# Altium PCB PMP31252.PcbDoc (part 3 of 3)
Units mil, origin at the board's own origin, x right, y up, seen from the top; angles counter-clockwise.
Board outline 4527.56 x 3188.98 mil, 6 copper layers (Top Layer, Layer 1, Layer 3, Layer 4, Layer 2, Bottom Layer), stack 32.112 mil thick; 215 components, 83 nets, 499 pads, 1248 vias.
Unrouted connection lines stored in the file: 2.
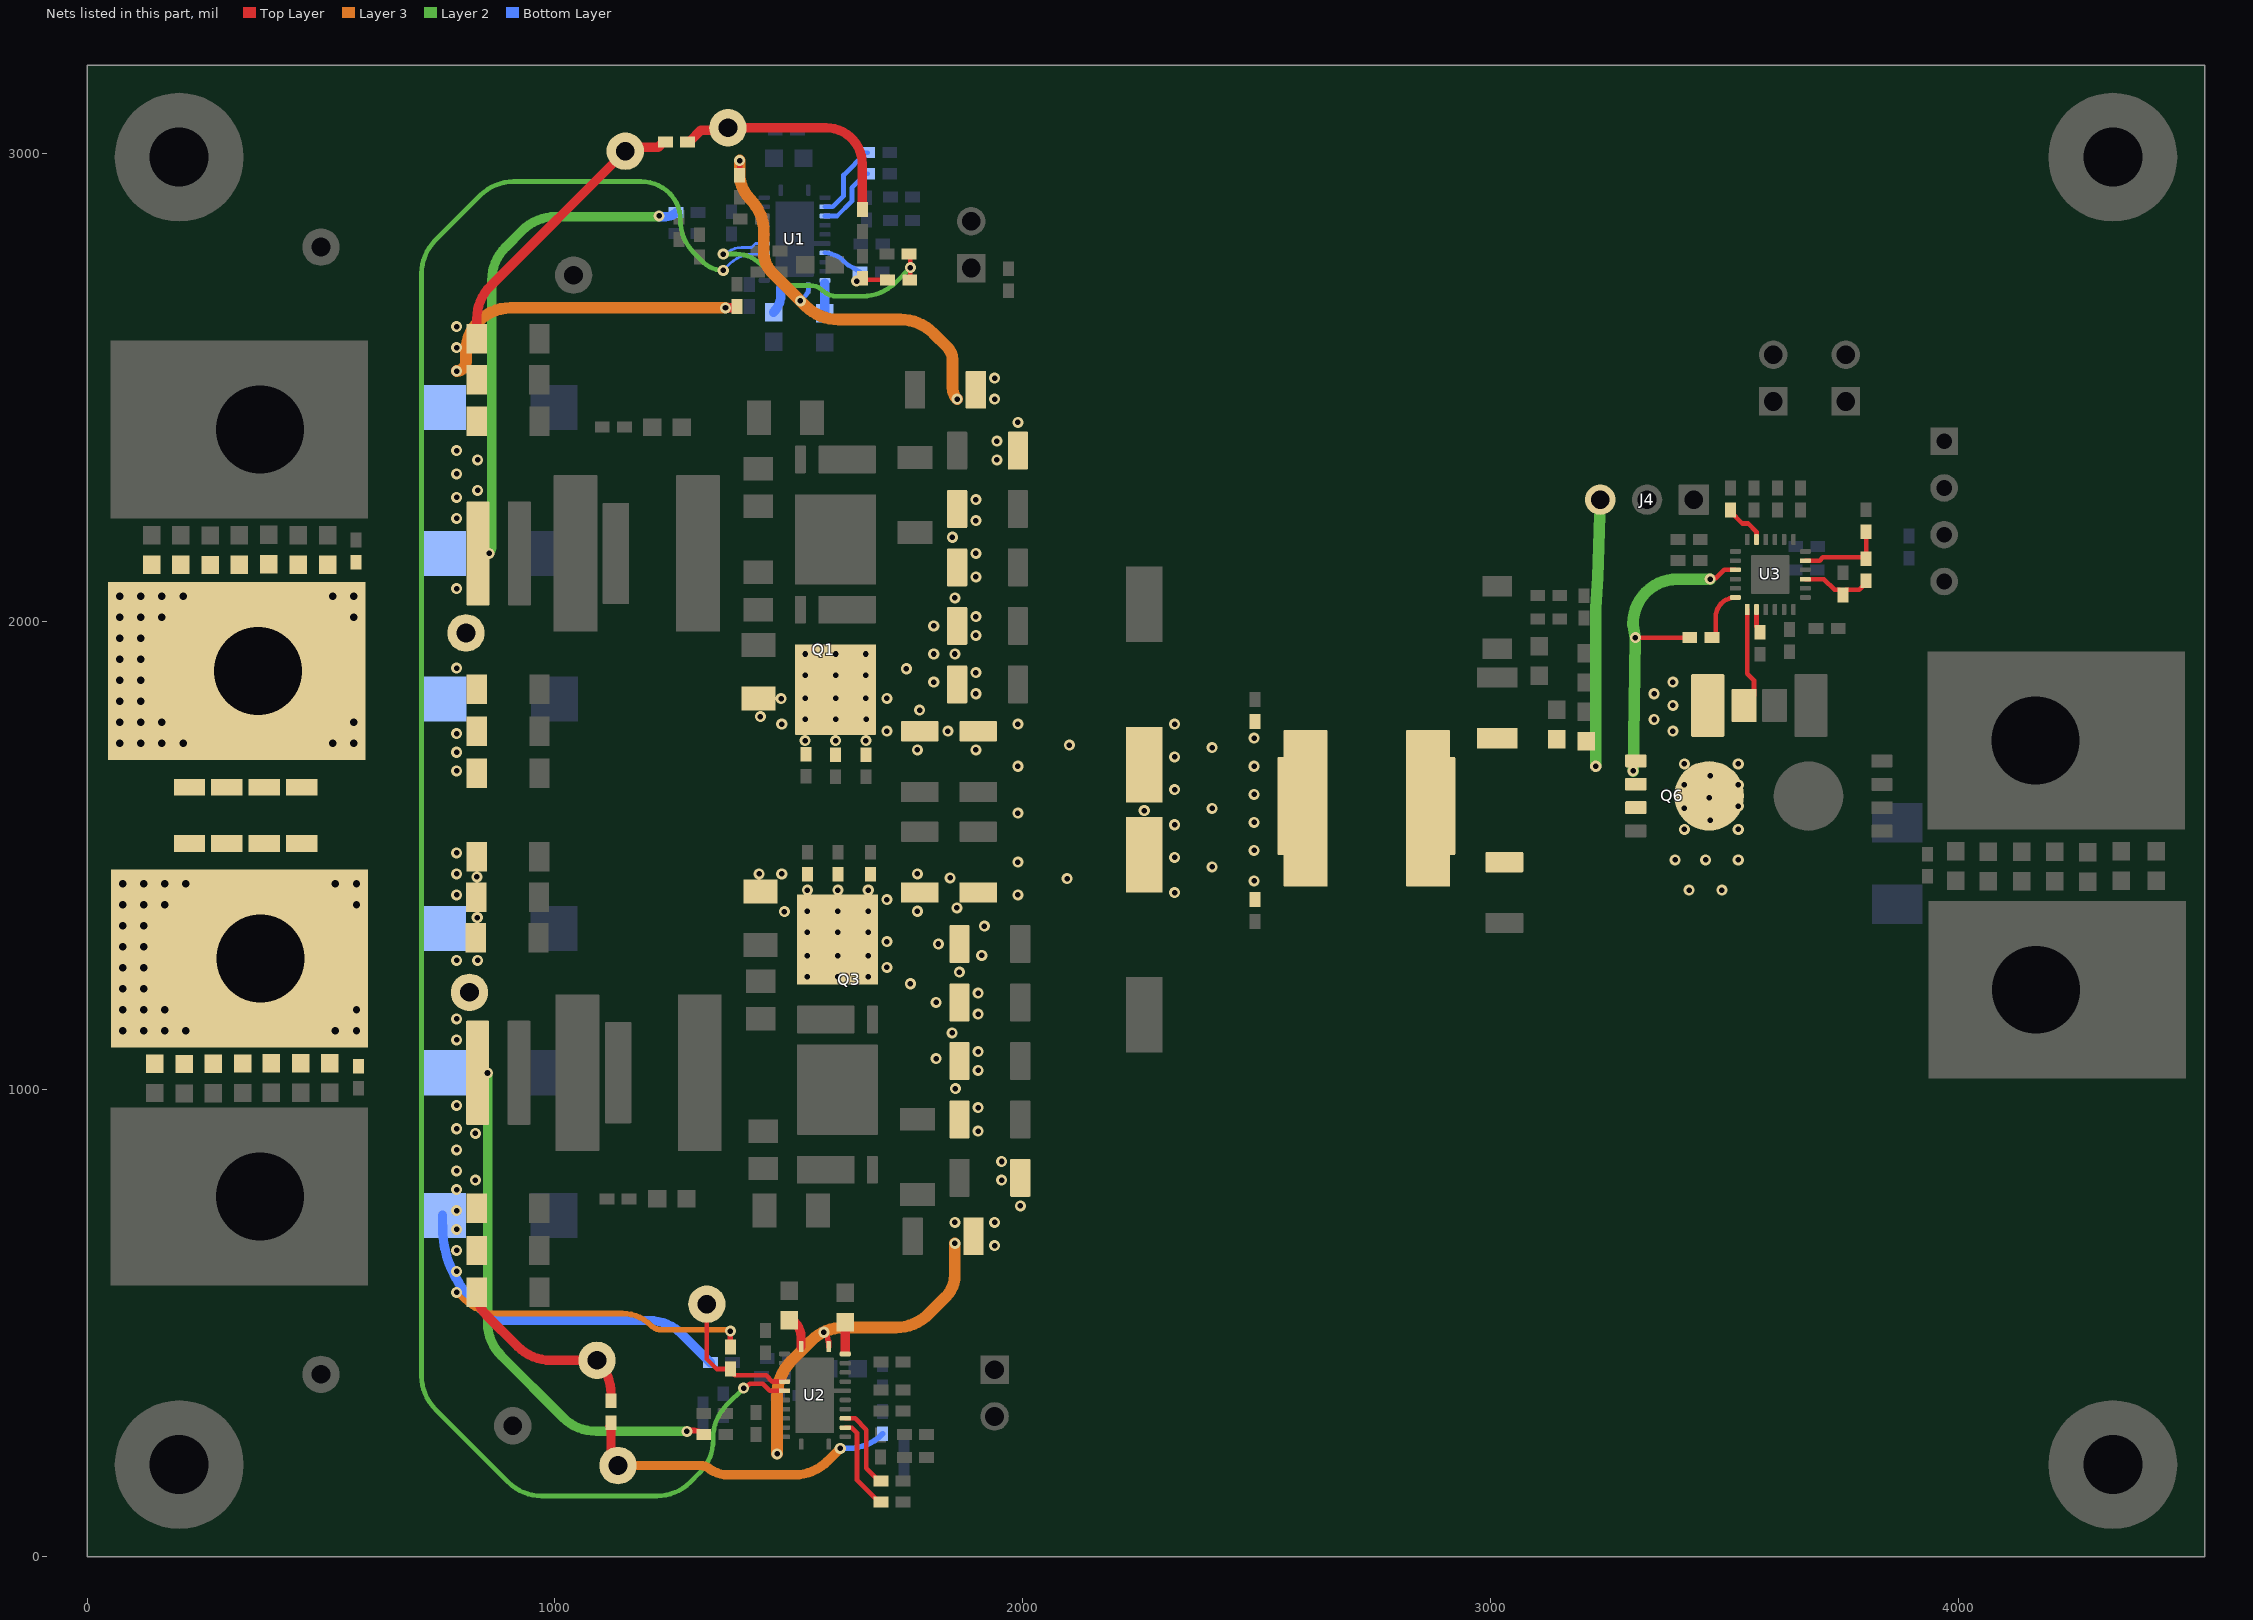
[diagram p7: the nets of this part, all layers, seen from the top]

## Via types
v1: diameter 23.62, hole 11.81, Top Layer to Bottom Layer, tented both sides, 1061 vias
v2: diameter 32, hole 16, Top Layer to Bottom Layer, 168 vias
v3: diameter 19.68, hole 7.87, Top Layer to Bottom Layer, 16 vias
v4: diameter 23.62/23.62/23.62/23.62/23.62/23.62 (per signal layer), hole 11.81, Top Layer to Bottom Layer, tented both sides, 3 vias

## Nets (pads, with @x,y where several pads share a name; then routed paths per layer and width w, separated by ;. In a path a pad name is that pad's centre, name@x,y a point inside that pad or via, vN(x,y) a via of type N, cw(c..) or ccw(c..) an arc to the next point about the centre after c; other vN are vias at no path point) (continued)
NetQ6_5: Q6.5 R56.2 R68.2 U3.19 | length 219.8
  Top Layer w10: R56.2@3542.52,1820 3563.48,1840.96 3563.48,1873.73 3549.29,1887.91 U3.19@3549.29,2025.2
  other v1: 3425,1425 3495,1425 3395,1490 3460,1490 3530,1490 3415,1555 3530,1555 3470,1575 3415,1600 3530,1605 3468.12,1623.09 3415,1650 3530,1650 3470,1670 3415,1695 3530,1695 3390,1765 3350,1790 3390,1820 3350,1845 3390,1870
NetR4_1: R4.1 U1.13 | length 56.5
  Bottom Layer w20: R4.1@1467.56,2660.43 ccw(c1430.21,2697.79) 1483.03,2697.79 U1.13@1483.03,2712.83
NetR9_1: R9.1 U1.11 | length 63.5
  Bottom Layer w20: R9.1@1576.75,2658.93 1576.75,2722.44
NetR12_1: R12.1 R16.2 TP2.1 | length 527
  Top Layer w20: R12.1@1283.62,3025 1287.56,3025 1312.56,3050 1365,3050 TP2.1@1370,3055 1580,3055 cw(c1580,2977.95) 1657.05,2977.95 R16.2@1657.05,2880.79
NetR19_2: R19.2 U1.4 | length 145.5
  Bottom Layer w10: U1.4@1577.52,2866.38 1603.12,2866.38 1635.18,2898.43 1635.18,2926.91 1664.96,2956.69 R19.2@1668.9,2956.69
NetR20_2: R20.2 U1.3 | length 165.4
  Bottom Layer w10: U1.3@1577.52,2886.06 1593.93,2886.06 1617.18,2909.31 1617.18,2953.91 1664.96,3001.69 R20.2@1668.9,3001.69
NetR36_1: R36.1 U2.13 | length 54.7
  Top Layer w20: R36.1@1513.55,500.61 cw(c1482.68,469.73) 1526.34,469.73 U2.13@1526.34,449.33
NetR39_1: R39.1 TP4.1 U2.17 | length 305.4
  Top Layer w10: TP4.1@1325,540 1325,422.76 1346.38,401.38 R39.1@1375,401.38 1375,397.44 1384.44,388 1451.61,388 1465.01,374.61 1490.83,374.61 U2.17@1490.91,374.53
NetR41_1: R41.1 U2.11 | length 60
  Top Layer w20: 1620.87,441.77 R41.1@1620.87,501.77
NetR46_1: R46.1 R50.1 TP6.1 | length 731.3
  Top Layer w10: R46.1@1112.68,279.06 1113.19,279.06 R46.1@1120,286.38 ; TP6.1@1135,195 1147.1,200.01 1148.51,201.42 TP6.1@1148.9,201.81
  Top Layer w20: R46.1@1120,286.38 1120,231.21 ccw(c1171.21,231.21) TP6.1@1135,195
  Layer 3 w20: TP6.1@1135,195 1310.86,195 cw(c1310.86,160.86) 1325.67,191.62 ; 1335,185 ccw(c1310.86,160.86) 1325.67,191.62 ; v1(1610.13,231.7) 1582.71,204.29 cw(c1512,275) 1512,175 1370.32,175 cw(c1370.32,243.28) 1325.67,191.62
  Bottom Layer w12: v1(1610.13,231.7) 1628,231.7 ccw(c1628,331.7) 1698.71,260.99 R50.1@1700.87,263.15
NetR47_2: R47.2 U2.3 | length 201.7
  Top Layer w10: U2.3@1620.83,276.1 1620.91,276.02 1635.18,276.02 1645.87,265.34 1645.87,164.21 1693.31,116.77 R47.2@1697.24,116.77
NetR48_2: R48.2 U2.4 | length 180.2
  Top Layer w10: U2.4@1620.83,295.79 1641.74,295.79 1665.87,271.66 1665.87,189.21 1693.31,161.77 R48.2@1697.24,161.77
NetR58_1: R58.1 U3.20 | length 56.1
  Top Layer w10: U3.20@3568.98,2025.2 3568.98,1988.58 3580,1977.56 R58.1@3580,1973.62
NetR60_2: R60.2 R61.2 U3.3 | length 159.6
  Top Layer w10: U3.3@3673.31,2090.16 3702.59,2090.16 3702.93,2089.81 3713.13,2089.81 3735.82,2067.13 3746.69,2067.13 R60.2@3753.5,2060.31 ; R60.2@3753.5,2056.38 R60.2@3753.5,2060.31 ; R61.2@3803.5,2086.38 3803.5,2082.44 3788.19,2067.13 3760.31,2067.13 R60.2@3753.5,2060.31
NetR61_1: R61.1 R62.2 U3.5 | length 192.1
  Top Layer w10: U3.5@3673.31,2129.53 3703.83,2129.53 3710.89,2136.58 3800.54,2136.58 R61.1@3803.5,2133.62 R62.2@3803.5,2191.38
NetR66_2: R66.2 U3.11 | length 93.4
  Top Layer w10: R66.2@3513.5,2237.76 3513.5,2233.82 3538.31,2209.01 3550.99,2209.01 3568.9,2191.1 3568.9,2174.88 U3.11@3568.98,2174.8
NetR71_1: R71.1 U3.18 | length 108.3
  Top Layer w10: R71.1@3481.65,1966.53 3481.65,2008.74 cw(c3523.7,2008.74) U3.18@3523.7,2050.79
PFM/SNYC: R21.2 R22.2 U1.18 | length 601.3
  Top Layer w10: R21.2@1757.24,2785 cw(c1750.53,2778.28) 1760.03,2778.28 v1(1760,2755.99) ; R22.2@1760,2730.03 v1(1760,2755.99)
  Layer 2 w10: v1(1360,2785) 1387.98,2785 cw(c1387.98,2711.8) 1439.74,2763.56 1479.01,2724.29 ccw(c1494.35,2739.63) 1494.35,2717.94 1546.03,2717.94 cw(c1546.03,2680.36) 1572.6,2706.93 ccw(c1601.4,2735.73) 1601.4,2695 1657.59,2695 ccw(c1657.59,2795) 1728.3,2724.29 v1(1760,2755.99)
  Bottom Layer w6: v1(1360,2785) 1365,2785 cw(c1399.05,2750.95) 1399.05,2799.11 1420.68,2799.11 1428.89,2807.32 U1.18@1447.6,2807.32
SYNC: U1.17 U2.18 | length 4349.1
  Top Layer w10: v1(1403.69,360.64) 1407.37,360.64 1416.73,370 1444.16,370 1459.24,354.92 1490.83,354.92 U2.18@1490.91,354.84
  Layer 2 w10: v1(1360,2750) cw(c1360,2810.35) 1317.33,2767.68 1297.19,2787.81 cw(c1368.29,2858.13) 1268.29,2858.13 1268.29,2858.77 ccw(c1188.77,2858.77) 1245,2915 ccw(c1184.64,2854.64) 1184.64,2940 911.42,2940 ccw(c911.42,2840) 840.71,2910.71 744.29,2814.29 ccw(c815,2743.58) 715,2743.58 715,386.42 ccw(c815,386.42) 744.29,315.71 900.71,159.29 ccw(c971.42,230) 971.42,130 1218.58,130 ccw(c1218.58,230) 1289.29,159.29 1309.11,179.11 ccw(c1238.4,249.82) 1338.4,249.82 1338.4,253.94 cw(c1438.4,253.94) 1348.81,298.37 cw(c1438.4,253.94) 1352.47,305.09 cw(c1438.4,253.94) 1367.69,324.65 v1(1403.69,360.64)
  Bottom Layer w6: v1(1360,2750) 1374.56,2764.56 ; 1374.58,2764.58 cw(c1422.82,2716.31) 1422.82,2784.55 1440.15,2784.55 ccw(c1440.15,2795.09) U1.17@1447.6,2787.64
VDDA: C25.1 R13.2 R22.1 U1.8 | length 165.9
  Top Layer w10: R13.2@1657.52,2733.07 ccw(c1664.93,2740.48) 1664.93,2730 R22.1@1711.38,2730
  Bottom Layer w10: U1.8@1577.52,2787.64 1589.73,2785.69 cw(c1587.36,2770.91) 1592.88,2784.82 1601.54,2781.39 cw(c1586.73,2744.02) 1614.67,2772.92 1624.58,2763.34 1625.31,2762.74 ccw(c1636.68,2776.69) 1628.12,2760.86 1641.77,2753.5 C25.1@1652.52,2746.69 1652.52,2745.35 cw(c1625.1,2745.35) 1644.49,2725.97 ccw(c1643.26,2727.19) v1(1645,2727.19)
Vin_FLT: C1.1 C2.2 C3.2 C4.2 C5.2 C6.2 C7.2 C8.2 C9.1 C28.2 C29.2 C30.2 C31.2 C32.2 C33.2 C34.2 C54.2 C56.2 C59.1 C60.1 C61.1 C62.1 C63.1 C64.1 C73.1 C99.1 L1.2 L6.2 Q1.5-6-7-8 Q3.5-6-7-8 R5.2 R30.2 R32.2 R33.2 U1.12 U2.12 | length 1646.7
  Top Layer w12: R5.2@1395,2953.62 v1(1395,2985) ; v1(1575,480) cw(c1549.91,454.91) 1585.39,454.91 U2.12@1585.39,449.33
  Layer 3 w25: v1(1395,2985) 1395,2956.76 ccw(c1471.67,2956.76) 1417.46,2902.54 cw(c1346.74,2831.83) 1446.74,2831.83 1446.74,2786.87 ccw(c1503.76,2786.87) 1463.44,2746.56 v1(1525,2685) 1535.71,2674.29 ccw(c1606.42,2745) 1606.42,2645 1738.58,2645 cw(c1738.58,2545) 1809.29,2615.71 1839.39,2585.61 cw(c1813.79,2560) 1850,2560 1850,2499.14 ccw(c1884.14,2499.14) v1(1860,2475) ; v1(1475,220) 1475,343.26 1475,343.33 cw(c1584.04,343.33) 1506.94,420.44 1548.31,461.81 cw(c1616.42,393.62) 1616.42,490 1728.58,490 ccw(c1728.58,590) 1799.29,519.29 1835.86,555.86 ccw(c1789.64,602.07) 1855,602.07 v1(1855,670)
  Bottom Layer w10: v1(1525,2685) 1534.49,2694.49 ccw(c1516.14,2712.83) U1.12@1542.09,2712.83
  Bottom Layer w12: v1(1475,220) R33.2@1475,256.38
  other v1: 1940,665 1855,715 1940,715 1995,750 1955,805 1955,845 1905,910 1905,960 1856.1,1000.71 1905,1040 1815,1065 1905,1080 1849.15,1119.86 1905,1160 1815,1185 1905,1205 1760,1225 1540,1240 1605,1240 1670,1240 1865,1250 1710,1260 1540,1285 1605,1285 1670,1285 1912.63,1285.85 1820,1310 1710,1315 1540,1335 1605,1335 1670,1335 1918.03,1348.2 1490.63,1379.05 1539.62,1379.58 1604.62,1379.58 1669.62,1379.58 1775,1380 1859.57,1387.05 1710,1405 1990,1415 2325,1420 1540,1425 1605,1425 1670,1425 2495,1445 2095,1450 1844.9,1451.28 1436.51,1460.02 1485,1460 1775,1460 2405,1475 1990,1485 2325,1495 2495,1510 2325,1565 2495,1570 1990,1590 2260,1595 2405,1600 2495,1630 2325,1640 1990,1690 2495,1690 2325,1710 1775,1725 1900,1725 2405,1730 2100,1735 1535,1745 1600,1745 1665,1745 2495,1750 1710,1765 1840,1765 1485,1780 1990,1780 2325,1780 1535.38,1790.42 1600.38,1790.42 1665.38,1790.42 1439.22,1796.13 1780,1810 1483.59,1834.76 1535,1835 1600,1835 1665,1835 1710,1835 1900,1845 1810,1870 1535,1885 1600,1885 1665,1885 1900,1890 1751.55,1898.43 1535,1930 1600,1930 1665,1930 1810,1930 1855,1930 1900,1970 1810,1990 1900,2010 1855,2050 1900,2095 1900,2145 1849.66,2179.62 1900,2215 1900,2260 1945,2345 1945,2385 1990,2425 1940,2475 1940,2520
VIN_PROT: C10.1 C11.1 C55.1 C101.1 J4.3 L1.1 L6.1 Q6.1 Q6.2 Q6.3 R71.2 U3.15 | length 1283.2
  Top Layer w10: v1(3310,1965) R71.2@3426.38,1965 ; v1(3470,2090) 3472.61,2092.61 3482.61,2092.61 3499.84,2109.84 U3.15@3523.7,2109.84
  Layer 2 w25: v1(3225.29,1690) 3225,1936.86 3225,2028.14 3229.31,2093.72 J4.3@3235,2260 ; v1(3305.29,1680) v1(3310,1965) 3305.39,1990.76 cw(c3330,1995.17) 3305,1994.82 3305,1995 cw(c3400,1995) 3400,2090 v1(3470,2090)
Vout_1: C18.1 C19.1 C20.1 C21.1 C27.1 C57.1 C65.1 C67.1 C68.1 C69.1 C78.1 C79.1 C80.1 C81.1 C82.1 C83.1 C84.1 R6.2 R10.2 R12.2 R25.2 R26.2 R27.2 R28.2 R29.2 T1.1 TP1.1 TP8.1 | length 2391.9
  Top Layer w12: R6.2@835.71,2145 v4(859.3,2145)
  Top Layer w20: C68.1@833.05,2603.97 833.05,2646.05 cw(c933.05,2646.05) 862.34,2716.76 TP1.1@1150.58,3005 1158.71,3013.14 1220.58,3013.14 1232.44,3025 R12.2@1236.38,3025 ; v1(1364.78,2670) 1387.72,2670 1389.53,2671.81 R10.2@1389.53,2673.06
  Layer 2 w12: v4(859.3,2145) ccw(c859.3,2147.77) v4@861.26,2145.81
  Layer 2 w20: v4(859.3,2145) ccw(c845.54,2158.76) 865,2158.76 865,2728.58 cw(c965,2728.58) 894.29,2799.29 930.71,2835.71 cw(c1001.42,2765) 1001.42,2865 1222.4,2865 1222.73,2865.33 v1(1222.73,2866.62)
  Layer 3 w25: v1(790,2535) ccw(c790,2555) 810,2555 810,2575 cw(c905,2575) 905,2670 v1(1364.78,2670)
  Bottom Layer w20: v1(1222.73,2866.62) 1222.75,2865 1237.36,2865 ccw(c1237.36,2895.51) R25.2@1258.94,2873.94
  other v1: 790,1680 790,1720 790,1760 790,1900 790,2070 790,2220 790,2265 835,2280 790,2315 835,2345 790,2365 790,2585 790,2630
  other v2: 70,1738.82 115,1738.82 160,1738.82 205,1738.82 525,1738.82 570,1738.82 70,1783.82 115,1783.82 160,1783.82 570,1783.82 70,1828.82 115,1828.82 70,1873.82 115,1873.82 70,1918.82 115,1918.82 70,1963.82 115,1963.82 70,2008.82 115,2008.82 160,2008.82 570,2008.82 70,2053.82 115,2053.82 160,2053.82 205,2053.82 525,2053.82 570,2053.82
Vout_2: C38.1 C39.1 C40.1 C41.1 C42.1 C58.1 C66.1 C70.1 C71.1 C72.1 C85.1 C86.1 C87.1 C88.1 C89.1 C90.1 C91.1 R26.1 R27.1 R28.1 R29.1 R37.2 R39.2 R40.2 R46.2 R52.2 T3.1 TP5.1 TP10.1 | length 2932
  Top Layer w12: v4@859.78,1034.78 v4@860,1035 ; v1(1282.45,268.26) 1284.18,270 1298.14,270 cw(c1298.14,241.91) R52.2@1318.01,261.77 ; R39.2@1375,448.62 v1(1375,482.3)
  Top Layer w20: C71.1@833.07,565 ccw(c900.84,565) 852.92,517.08 920.71,449.29 ccw(c991.42,520) 991.42,420 TP5.1@1090,420 1090.71,419.29 cw(c1020,348.58) 1120,348.58 R46.2@1120,333.62 ; R37.2@855.62,1033.9 v4(855.95,1034.23)
  Layer 2 w20: v4(855.95,1034.23) ccw(c852.55,1037.63) 856.21,1034.52 856.21,500.21 ccw(c956.21,500.21) 885.5,429.5 1017.45,297.55 ccw(c1088.16,368.26) 1088.16,268.26 v1(1282.45,268.26)
  Layer 3 w12: v1(790,565) 805.71,549.29 ccw(c876.42,620) 876.42,520 1144.64,520 cw(c1144.64,434.64) 1205,495 ccw(c1228.3,518.3) 1228.3,485.35 1373.74,485.35 cw(c1370.69,482.3) v1(1375,482.3)
  Bottom Layer w20: C66.1@759.89,729.85 760.35,691.62 760.35,691.51 ccw(c986.69,705.98) 826.32,545.61 826.39,545.53 844.33,527.6 ccw(c898.88,582.16) 898.88,505 1201.33,505 cw(c1201.33,405) 1272.05,475.71 R40.2@1332.76,415
  other v1: 790,610 790,655 790,700 790,740 790,785 830,805 790,825 790,870 830,905 790,915 790,965 790,1105 790,1150 790,1275 835,1275 834.01,1366.53 790,1415 833.4,1453.48 790,1460 790,1505
  other v2: 75.92,1124.2 120.92,1124.2 165.92,1124.2 210.92,1124.2 530.92,1124.2 575.92,1124.2 75.92,1169.2 120.92,1169.2 165.92,1169.2 575.92,1169.2 75.92,1214.2 120.92,1214.2 75.92,1259.2 120.92,1259.2 75.92,1304.2 120.92,1304.2 75.92,1349.2 120.92,1349.2 75.92,1394.2 120.92,1394.2 165.92,1394.2 575.92,1394.2 75.92,1439.2 120.92,1439.2 165.92,1439.2 210.92,1439.2 530.92,1439.2 575.92,1439.2
pads on no net: U2.1 U2.2 U2.22 U2.23 U2.24 U3.8 U3.17 U3.21 U3.25

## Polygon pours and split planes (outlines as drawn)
GND on Top Layer "NONET_L01_P-001" (solid, pour order 84): 3010.88,3148.33 2925,3148.33 ccw(c2925,3048.33) 2825,3048.33 2825,1860 ccw(c2840,1860) 2840,1845 2945,1845 cw(c2945,1835) 2955,1835 2955,1370 cw(c2940,1370) 2940,1355 2835,1355 ccw(c2835,1330) 2810,1330 2810,110 ccw(c2870,110) 2870,50 4390,50 ccw(c4390,150) 4490,150 4490,3045 ccw(c4390,3045) 4390,3145 4220,3145
NetC37_1 on Top Layer "NONET_L01_P-001" (solid, pour order 57): 1126.88,763.59 1126.88,825.67 cw(c1194.74,825.67) 1146.75,873.66 ccw(c1143.52,870.43) 1143.52,875 1035,875 cw(c1035,814.25) 1095.75,814.25 1095.75,767
NetC37_1 on Top Layer "NONET_L01_P-001" (solid, pour order 7): 898.98,914.78 ccw(c948.98,914.78) 948.98,864.78 1119.78,864.78 ccw(c1119.78,910) 1165,910 1165,1160 ccw(c1119.73,1159.95) 1119.78,1205.22 943.98,1204.78 ccw(c946.48,1157.28) 898.98,1154.78
NetC15_1 on Top Layer "NONET_L01_P-001" (solid, pour order 14): 900,2025 ccw(c950,2025) 950,1975 1120.79,1975 ccw(c1120.79,2020.22) 1166.02,2020.22 1166.02,2270.22 ccw(c1120.75,2270.17) 1120.79,2315.44 945,2315 ccw(c947.5,2267.5) 900,2265
GND on Top Layer "NONET_L01_P-001" (solid, pour order 87): 1510,750 1510,710 cw(c1475,710) 1475,675 1438.28,675 cw(c1431.21,726.21) 1400,685 ccw(c1350.86,634.65) 1350,705 1285,705 1285,50 1815,50 1815,673.58 ccw(c1715,673.58) 1785.71,744.29 1780,750
AGND2 on Top Layer "NONET_L01_P-001" (solid, pour order 30): 1679.37,428.23 1679.37,108.23 ccw(c1694.37,108.23) 1694.37,93.23 1754.37,93.23 ccw(c1754.37,158.23) 1819.37,158.23 1819.37,389.13 ccw(c1770.08,389.14) 1770.08,438.43 1689.57,438.43 ccw(c1689.57,428.23)
GND on Top Layer "NONET_L01_P-001" (solid, pour order 77): 580,1011.22 cw(c578.64,989.86) 600,988.5 600,550 ccw(c665,550) 665,485 859.37,485 ccw(c859.37,525.63) 900,525.63 900,805 cw(c930,805) 930,835 1040,835 cw(c1040,805) 1070,805 1070,735 ccw(c1100,735) 1100,705 1300,705 cw(c1300,605) 1400,605 1400,50 145,50 cw(c145,150) 45,150 45,955 cw(c100,955) 100,1010
GND on Top Layer "NONET_L01_P-001" (solid, pour order 88): 2110,3150 1695,3150 1695,2495 1773.79,2495 ccw(c1773.79,2546.21) 1810,2510 1810,2540 cw(c1845,2540) 1845,2575 1940,2575 cw(c1940,2475) 2040,2475 2040,2445 2110,2445
GND on Top Layer "NONET_L01_P-001" (solid, pour order 86): 2530,1845 ccw(c2530,1830) 2515,1830 2515,1824.26 cw(c2507.53,1824.26) 2507.53,1816.8 1975.01,1816.8 cw(c1975.01,1838.62) 1953.19,1838.62 1953.19,2253.19 cw(c1990,2253.19) 1990,2290 2000,2290 ccw(c2000,2330) 2040,2330 2040,3150 2945,3150 2945,1885 cw(c2905,1885) 2905,1845
GND on Top Layer "NONET_L01_P-001" (solid, pour order 85): 2935,1355 2540,1355 cw(c2540,1370) 2525,1370 ccw(c2520,1370) 2520,1375 2020,1375 ccw(c2020,1305) 1950,1305 1950,920 ccw(c1980,920) 1980,890 2000,890 cw(c2000,855) 2035,855 2035,710 cw(c1935,710) 1935,610 1837.28,610 cw(c1837.28,632.28) 1815,632.28 1815,665 1780,665 cw(c1780,660) 1785,660 1785,50 2935,50
NetC15_1 on Top Layer "NONET_L01_P-001" (solid, pour order 82): 1102.16,2451.89 ccw(c1102.16,2434.73) 1085,2434.73 1085,2345 cw(c1055,2345) 1055,2315 1055,2295 1140,2295 cw(c1140,2309.75) 1125.25,2309.75 1125.25,2315.44 cw(c1125.25,2323.44) 1117.24,2323.44 1117.24,2437.15 ccw(c1102.62,2437.15) 1102.62,2451.77
GND on Top Layer "NONET_L01_P-001" (solid, pour order 80): 1505,2450 1505,2455 ccw(c1465,2455) 1465,2495 1090,2495 ccw(c1090,2465) 1060,2465 1060,2408.69 cw(c1028.59,2408.69) 1028.59,2377.28 922.72,2377.28 cw(c922.72,2400) 900,2400 900,2635 ccw(c835,2635) 835,2700 670,2700 ccw(c670,2630) 600,2630 600,2175 cw(c580,2175) 580,2155 90,2155 cw(c90,2200) 45,2200 45,3049.34 cw(c145,3049.34) 145,3149.34 1750.66,3149.34 cw(c1750.66,3095) 1805,3095 1805,2690 cw(c1745,2690) 1745,2630 1745,2435
GND on Top Layer "NONET_L01_P-001" (solid, pour order 72): 1555,1685 1355,1685 cw(c1355,1725) 1315,1725 1315,1910 ccw(c1275,1910) 1275,1950 905.8,1950 ccw(c905.8,1924.2) 880,1924.2 880,1270 ccw(c910,1270) 910,1240 1320,1240 ccw(c1320,1265) 1345,1265 1345,1460 cw(c1372.5,1462.5) 1370,1490 1555,1490
GND on Top Layer "NONET_L01_P-001" (solid, pour order 39): 1520,860 ccw(c1520,850) 1510,850 1510,650 ccw(c1535,650) 1535,625 1790,625 ccw(c1790,650) 1815,650 1815,830 ccw(c1785,830) 1785,860
Vout_1 on Top Layer "NONET_L01_P-001" (solid, pour order 65): 619.08,2163.02 cw(c594.08,2163.02) 594.08,2138.02 94.08,2138.02 ccw(c94.08,2083.02) 39.08,2083.02 39.08,1653.02 ccw(c79.08,1653.02) 79.08,1613.02 824.08,1613.02 ccw(c824.08,1648.02) 859.08,1648.02 859.08,2638.02 ccw(c829.08,2638.02) 829.08,2668.02 654.08,2668.02 ccw(c654.08,2633.02) 619.08,2633.02
Vout_2 on Top Layer "NONET_L01_P-001" (solid, pour order 64): 625,1010 ccw(c600,1010) 600,1035 100,1035 cw(c100,1090) 45,1090 45,1520 cw(c85,1520) 85,1560 830,1560 cw(c830,1525) 865,1525 865,520 cw(c850,520) 850,505 660,505 cw(c660,540) 625,540
NetC14_1 on Top Layer "NONET_L01_P-001" (solid, pour order 61): 1249.67,2283.33 1249.67,2428.33 cw(c1254.67,2428.33) 1254.67,2433.33 1289.67,2433.33 cw(c1289.67,2428.33) 1294.67,2428.33 1294.67,2333.33 ccw(c1309.67,2333.33) 1309.67,2318.33
NetC35_1 on Top Layer "NONET_L01_P-001" (solid, pour order 58): 1260,890 1260,745 ccw(c1265,745) 1265,740 1300,740 ccw(c1300,745) 1305,745 1305,840 cw(c1320,840) 1320,855
VIN_PROT on Top Layer "NONET_L01_P-001" (solid, pour order 56): 3333.15,1587.19 3292.19,1587.19 ccw(c3292.19,1560) 3265,1560 3265,1530 cw(c3165,1530) 3165,1430 2820,1430 cw(c2820,1440) 2810,1440 2810,1755 cw(c2825,1755) 2825,1770 3215,1770 cw(c3215,1760) 3225,1760 3225,1750 ccw(c3260,1750) 3260,1715 3335,1715 cw(c3335,1710) 3340,1710 3340,1594.04 cw(c3333.04,1594.15)
NetC49_1 on Top Layer "NONET_L01_P-001" (solid, pour order 53): 3860,1905 cw(c3860,1865) 3900,1865 3900,1760 cw(c3875,1760) 3875,1735 3800,1735 ccw(c3800,1715) 3780,1715 3780,1305 cw(c3760,1305) 3760,1285 3600,1285 cw(c3600,1303.69) 3581.31,1303.69 3581.31,1836.31 cw(c3600,1836.31) 3600,1855 3620,1855 ccw(c3620,1885) 3650,1885 cw(c3670,1885) 3670,1905 3705,1905
NetC48_1 on Top Layer "NONET_L01_P-001" (solid, pour order 55): 3865,1665 ccw(c3865,1730) 3930,1730 3930,1930 cw(c3945,1930) 3945,1945 4480,1945 cw(c4480,1930) 4495,1930 4495,1530 cw(c4450,1530) 4450,1485 3835,1485 cw(c3835,1510) 3810,1510 3810,1660 cw(c3815,1660) 3815,1665
NetQ6_5 on Top Layer "NONET_L01_P-001" (solid, pour order 54): 3287.98,1905.34 ccw(c3287.98,1865.34) 3247.98,1865.34 3247.98,1760.34 ccw(c3272.98,1760.34) 3272.98,1735.34 3347.98,1735.34 cw(c3347.98,1715.34) 3367.98,1715.34 3367.98,1305.34 ccw(c3387.98,1305.34) 3387.98,1285.34 3547.98,1285.34 ccw(c3547.98,1304.03) 3566.68,1304.03 3566.68,1836.64 ccw(c3547.98,1836.64) 3547.98,1855.34 3527.98,1855.34 cw(c3527.98,1885.34) 3497.98,1885.34 ccw(c3477.98,1885.34) 3477.98,1905.34 3442.98,1905.34
GND on Top Layer "NONET_L01_P-001" (solid, pour order 50): 1858.88,2405.57 cw(c1858.88,2455.57) 1808.88,2455.57 1783.88,2455.57 ccw(c1783.88,2440.57) 1768.88,2440.57 1768.88,2315.57 1868.88,2315.57 ccw(c1868.88,2330.57) 1883.88,2330.57 1883.88,2400.57 ccw(c1878.88,2400.57) 1878.88,2405.57
GND on Top Layer "NONET_L01_P-001" (solid, pour order 49): 1513.88,2315.57 cw(c1513.88,2325.57) 1503.88,2325.57 1503.88,2525.57 cw(c1528.88,2525.57) 1528.88,2550.57 1783.88,2550.57 cw(c1783.88,2525.57) 1808.88,2525.57 1808.88,2345.57 cw(c1778.88,2345.57) 1778.88,2315.57
Vin_FLT on Top Layer "NONET_L01_P-001" (solid, pour order 48): 1838.63,2280.16 1838.63,2281.48 cw(c1863.76,2281.48) 1863.76,2306.61 1881.72,2306.61 ccw(c1881.72,2326.84) 1901.95,2326.84 1901.95,2393.36 ccw(c1865.13,2393.36) 1865.12,2430.18 1858.63,2430.18 cw(c1858.63,2450.18) 1838.63,2450.18 1838.63,2525.18 cw(c1863.63,2525.18) 1863.63,2550.18 1923.63,2550.18 cw(c1923.63,2455.18) 2018.63,2455.18 2018.63,2330.18 cw(c1998.63,2330.18) 1998.63,2310.18 1989.84,2310.18 ccw(c1989.84,2258.97) 1953.63,2295.18 1952.92,2294.47 ccw(c2023.63,2223.76) 1923.63,2223.76 1923.63,2125.18
GND on Top Layer "NONET_L01_P-001" (solid, pour order 47): 1865,770 ccw(c1865,720) 1815,720 1790,720 cw(c1790,735) 1775,735 1775,860 1875,860 cw(c1875,845) 1890,845 1890,775 cw(c1885,775) 1885,770
Vin_FLT on Top Layer "NONET_L01_P-001" (solid, pour order 46): 1840,895.03 1840,893.7 ccw(c1865.13,893.7) 1865.13,868.57 1883.09,868.57 cw(c1883.09,848.35) 1903.32,848.34 1903.32,781.83 cw(c1866.5,781.82) 1866.49,745 1860,745 ccw(c1860,725) 1840,725 1840,650 ccw(c1865,650) 1865,625 1925,625 ccw(c1925,720) 2020,720 2020,845 ccw(c2000,845) 2000,865 1991.21,865 cw(c1991.21,916.21) 1955,880 1954.29,880.71 cw(c2025,951.42) 1925,951.42 1925,1050
Vin_FLT on Top Layer "NONET_L01_P-001" (solid, pour order 35): 1547.97,1475.16 1384.61,1475.29 ccw(c1387.44,1447.84) 1360,1445 1360,1410 ccw(c1395,1410) 1395,1375 1461.02,1375 cw(c1461.02,1329.95) 1506.07,1329.95 1506.07,1228.93 ccw(c1520,1228.93) 1520,1215 1680,1215 cw(c1672.59,1152.41) 1735.18,1145 1735.18,1114.82 ccw(c1762.8,1116.26) 1744.29,1095.71 1811.72,1028.28 cw(c1743.48,960.02) 1840,960 1840,900 ccw(c1865,900) 1865,875 1895,875 ccw(c1892.5,907.5) 1925,910 1925,1304.64 cw(c2010.36,1304.64) 1950,1365 ccw(c1930.34,1384.67) 1958.15,1384.67 1958.15,1416.1 ccw(c1899.25,1416.1) 1899.25,1475 1760,1475
NetC77_2 on Top Layer "NONET_L01_P-001" (solid, pour order 45): 1410,848.84 cw(c1420,848.84) 1420,858.84 1470,858.84 cw(c1470,848.84) 1480,848.84 1480,710 cw(c1465,710) 1465,695 1425,695 cw(c1425,710) 1410,710
NetC76_1 on Top Layer "NONET_L01_P-001" (solid, pour order 40): 1475,1335 cw(c1475,1330) 1480,1330 1480,1215.05 cw(c1469.1,1215.05) 1469.1,1204.14 1410.86,1204.14 cw(c1410.86,1215) 1400,1215 1400,1330 cw(c1405,1330) 1405,1335
Vin_FLT on Top Layer "NONET_L01_P-001" (solid, pour order 38): 2650,1765 ccw(c2615,1765) 2615,1800 1925,1800 1925,1704.94 cw(c1918.02,1704.94) 1922.95,1700 1930,1700 cw(c1930,1665) 1965,1665 1965,1495 cw(c1945,1495) 1945,1475 1880,1475 1880,1405 ccw(c1895,1405) 1895,1390 1925,1390 cw(c1925,1365) 1950,1365 1957.32,1372.32 cw(c2000,1329.64) 2000,1390 2605,1390 ccw(c2605,1435) 2650,1435
GND on Top Layer "NONET_L01_P-001" (solid, pour order 37): 1526.62,1685.53 1924.47,1685.53 cw(c1924.47,1660) 1950,1660 1950,1520 cw(c1920,1520) 1920,1490 1525,1490 cw(c1525,1510) 1505,1510 1505,1663.69 cw(c1526.68,1663.69) 1526.68,1685.37
NetC35_1 on Top Layer "NONET_L01_P-001" (solid, pour order 36): 1573.94,1178.61 1391.39,1178.61 cw(c1391.39,1200) 1370,1200 ccw(c1355,1200) 1355,1215 1285,1215 ccw(c1285,1190) 1260,1190 1260,875 ccw(c1280,875) 1280,855 1333.79,855 ccw(c1333.79,906.21) 1370,870 cw(c1394.14,845.86) 1394.14,880 1470.86,880 ccw(c1470.86,914.14) 1495,890 cw(c1519.14,865.86) 1519.14,900 1800,900 ccw(c1800,920) 1820,920 1820,933.58 ccw(c1720.01,933.58) 1790.71,1004.29 1706.61,1088.39 ccw(c1690.75,1072.54) 1690.75,1094.96 1664.8,1094.96 cw(c1661.71,1111.31) 1645.36,1108.22 1645.12,1169.16 ccw(c1635.67,1169.16) 1635.67,1178.61
NetC75_2 on Top Layer "NONET_L01_P-001" (solid, pour order 20): 1469.88,2308.74 cw(c1459.88,2308.74) 1459.88,2298.74 1409.88,2298.74 cw(c1409.88,2308.74) 1399.88,2308.74 1399.88,2458.74 cw(c1414.88,2458.74) 1414.88,2473.74 1454.88,2473.74 cw(c1454.88,2458.74) 1469.88,2458.74
NetC14_1 on Top Layer "NONET_L01_P-001" (solid, pour order 24): 1400,2275 cw(c1392.5,2307.5) 1360,2300 ccw(c1340,2300) 1340,2320 1270,2320 ccw(c1270,2300) 1250,2300 1250,1985 ccw(c1270,1985) 1270,1965 1330,1965 ccw(c1330,2000) 1365,2000 1365,2030 cw(c1410,2030) 1410,2075 1530,2075 cw(c1530,2045) 1560,2045 1560,2000 ccw(c1570,2000) 1570,1990 1658.58,1990 ccw(c1658.58,2090) 1729.29,2019.29 1782.54,2072.54 ccw(c1711.83,2143.25) 1811.83,2143.25 1811.83,2195.2 ccw(c1744.3,2195.2) 1792.05,2242.95 1775,2260 ccw(c1738.79,2223.79) 1738.79,2275 1675,2275
Vin_FLT on Top Layer "NONET_L01_P-001" (solid, pour order 26): 1837.06,2273.86 1837.06,2113.48 cw(c1737.08,2113.48) 1807.77,2042.77 1744.29,1979.29 cw(c1673.58,2049.99) 1673.58,1950 1517.07,1950 ccw(c1517.07,1932.94) 1505,1945 ccw(c1517.06,1932.93) 1500,1932.93 1500,1914.14 cw(c1465.87,1914.14) 1490,1890 1485.61,1885.61 cw(c1460,1911.2) 1460,1875 1350,1875 ccw(c1350,1855) 1330,1855 1330,1725 ccw(c1355,1725) 1355,1700 1920,1700 ccw(c1920,1730) 1950,1730 1950,1778.79 ccw(c1898.8,1778.79) 1935,1815 cw(c1959.14,1839.14) 1925,1839.14 1925,2275 ccw(c1901.85,2275) 1901.85,2298.15 1856.1,2298.15 ccw(c1858.72,2276.49)
NetC74_1 on Top Layer "NONET_L01_P-001" (solid, pour order 29): 1400,1922.09 cw(c1400,1927.09) 1395,1927.09 1395,2042.04 cw(c1405.9,2042.04) 1405.9,2052.94 1464.14,2052.94 cw(c1464.14,2042.09) 1475,2042.09 1475,1927.09 cw(c1470,1927.09) 1470,1922.09
GND on Bottom Layer "NONET_L01_P-001" (solid, remove dead copper, pour order 90): 145,3150 ccw(c145,3050) 45,3050 45,150 ccw(c145,150) 145,50 4390,50 ccw(c4390,150) 4490,150 4490,3050 ccw(c4390,3050) 4390,3150 3955,3150
NetQ6_5 on Bottom Layer "NONET_L01_P-001" (solid, pour order 74): 3565,1070.14 cw(c3530.64,1070.14) 3530.64,1035.79 3109.21,1035.79 cw(c3109.21,1070) 3075,1070 3075,1885 cw(c3105,1885) 3105,1915 3535,1915 cw(c3535,1885) 3565,1885
NetC48_1 on Bottom Layer "NONET_L01_P-001" (solid, pour order 31): 3938.79,1520 ccw(c3938.79,1571.21) 3975,1535 cw(c4023.28,1486.72) 4023.28,1555 4200,1555 4039.29,1715.71 ccw(c3968.58,1645) 3968.58,1745 3935.4,1745 cw(c3839.79,1745) 3907.39,1677.39 3875,1645 cw(c3850.86,1669.14) 3850.86,1635 3819.27,1635 ccw(c3819.27,1621.77) 3806.04,1621.77 3806.04,1538.96 ccw(c3825,1538.96) 3825,1520
AGND1 on Bottom Layer "NONET_L01_P-001" (solid, pour order 41): 1642.56,2738.94 ccw(c1672.56,2738.94) 1672.56,2708.94 1692.56,2708.94 ccw(c1692.56,2808.94) 1792.56,2808.94 1792.56,3011.63 ccw(c1771.75,3011.63) 1771.75,3032.44 1674.05,3032.44 ccw(c1674.05,3001.69) 1643.31,3001.69
NetC49_1 on Bottom Layer "NONET_L01_P-001" (solid, pour order 89): 3619.72,1905 ccw(c3619.72,1871.18) 3585.91,1871.18 3585.91,1059.09 ccw(c3610,1059.09) 3610,1035 3750,1035 ccw(c3750,1060) 3775,1060 3775,1699.17 cw(c3806.04,1699.17) 3806.04,1730.21 3860.21,1730.21 ccw(c3860.21,1770) 3900,1770 3900,1865 ccw(c3860,1865) 3860,1905
Vout_2 on Bottom Layer "NONET_L01_P-001" (solid, pour order 42): 625,1010 ccw(c600,1010) 600,1035 100,1035 cw(c100,1090) 45,1090 45,1520 cw(c85,1520) 85,1560 830,1560 cw(c830,1525) 865,1525 865,535 cw(c835,535) 835,505 660,505 cw(c660,540) 625,540
Vout_1 on Bottom Layer "NONET_L01_P-001" (solid, pour order 69): 619.32,2163.02 cw(c594.32,2163.02) 594.32,2138.02 94.32,2138.02 ccw(c94.32,2083.02) 39.32,2083.02 39.32,1653.02 ccw(c79.32,1653.02) 79.32,1613.02 824.32,1613.02 ccw(c824.32,1648.02) 859.32,1648.02 859.32,2638.02 ccw(c829.32,2638.02) 829.32,2668.02 654.32,2668.02 ccw(c654.32,2633.02) 619.32,2633.02
NetQ6_5 on Layer 3 "NONET_L01_P-001" (solid, pour order 70): 3565,1070.14 cw(c3530.64,1070.14) 3530.64,1035.79 3109.21,1035.79 cw(c3109.21,1070) 3075,1070 3075,1885 cw(c3105,1885) 3105,1915 3535,1915 cw(c3535,1885) 3565,1885
Vin_FLT on Layer 3 "NONET_L01_P-001" (solid, pour order 68): 2655,1236.42 cw(c2555,1236.42) 2625.71,1165.71 2110,650 cw(c2038.08,721.21) 2038.58,620 1540,620 cw(c1540,735) 1425,735 1425,2435 cw(c1540,2435) 1540,2550 2058.58,2550 cw(c2058.58,2450.01) 2129.29,2520.71 2625.71,2024.29 cw(c2555.01,1953.58) 2655,1953.58 2655,1660
NetC49_1 on Layer 3 "NONET_L01_P-001" (solid, pour order 71): 3585,1875 cw(c3620,1875) 3620,1910 3870,1910 cw(c3870,1880) 3900,1880 3900,1070 cw(c3865,1070) 3865,1035 3625,1035 cw(c3625,1075) 3585,1075
Vout_1 on Layer 3 "NONET_L01_P-001" (solid, pour order 44): 619.08,2163.02 cw(c594.08,2163.02) 594.08,2138.02 94.08,2138.02 ccw(c94.08,2083.02) 39.08,2083.02 39.08,1653.02 ccw(c79.08,1653.02) 79.08,1613.02 824.08,1613.02 ccw(c824.08,1648.02) 859.08,1648.02 859.08,2638.02 ccw(c829.08,2638.02) 829.08,2668.02 654.08,2668.02 ccw(c654.08,2633.02) 619.08,2633.02
Vout_2 on Layer 3 "NONET_L01_P-001" (solid, pour order 43): 625,1010 ccw(c600,1010) 600,1035 100,1035 cw(c100,1090) 45,1090 45,1520 cw(c85,1520) 85,1560 830,1560 cw(c830,1525) 865,1525 865,520 cw(c850,520) 850,505 660,505 cw(c660,540) 625,540
GND on Layer 4 "NONET_L01_P-001" (solid, pour order 62): 155,3150 4390,3150 cw(c4390,3050) 4490,3050 4490,150 cw(c4390,150) 4390,50 145,50 cw(c145,150) 45,150 45,3040 cw(c155,3040)
GND on Layer 2 "NONET_L01_P-001" (solid, pour order 63): 155,3150 4390,3150 cw(c4390,3050) 4490,3050 4490,150 cw(c4390,150) 4390,50 145,50 cw(c145,150) 45,150 45,3040 cw(c155,3040)
GND on Layer 1 "NONET_L01_P-001" (solid, pour order 78): 155,3150 4390,3150 cw(c4390,3050) 4490,3050 4490,150 cw(c4390,150) 4390,50 145,50 cw(c145,150) 45,150 45,3040 cw(c155,3040)

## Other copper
Bottom Layer:
  pour cut-out: 3500,1930 3540.94,1930 cw(c3540.94,1899.34) 3562.62,1921.02 ccw(c3570.32,1928.72) 3570.32,1917.83 3846.41,1917.83 ccw(c3846.41,2017.83) 3917.12,1947.12 3920,1950 3920,1910 3571.21,1910 cw(c3571.21,1961.21) 3535,1925 3512.07,1925 cw(c3512.07,1942.07)
  pour cut-out: 3505,1020 3635,1020 3635,1030 3505,1030

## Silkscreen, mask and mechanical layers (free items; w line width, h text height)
Top Overlay:
  lines w10: 4065,2330 4340,2330 ; 4065,2445 4340,2445
  text "J4: Sleep mode OVP" at 2240,3054.99 h60
  text "1-2: Cut-off" at 2485,2950 h60
  text "2-3: Clamp" at 2475,2854.99 h60
  text "EN1" at 2025,2800 h60 r90
  text "J5: Short to latch off" at 2240,2740 h60
  text "J6: Current monitor" at 2240,2625 h60
  text "FAULT" at 4060,2365 h60
  text "GND" at 686.94,2313.43 h98.43 r90
  text "SLEEP" at 4060,2250 h60
  text "EN" at 4060,2145 h60
  text "GND" at 4060,2050 h60
  text "+" at 4295,1929.37 h393.7
  text "+" at 20.2,1466.96 h393.7
  text "INPUT" at 3315,1257.1 h196.85
  text "GND" at 681.07,675.39 h98.43 r90
  text "PG" at 1145,505 h60
  text "PMP31252" at 2200,481.15 h531.5
  text "Rev. E1" at 2200,317 h196.85
  text "EN2" at 2080.71,270.71 h60 r90
Mechanical 1:
  the board outline again, w10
